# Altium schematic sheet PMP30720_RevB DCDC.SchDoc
size 431 x 279 mm; Date: Not shown in title block; ApprovedBy: Not shown in title block; CheckedBy: Not shown in title block; Author: Not shown in title block; CompanyName: Not shown in title block; Engineer: Not shown in title block; Organization: Not shown in title block; Address1: Not shown in title block; Address2: Not shown in title block; Address3: Not shown in title block; Address4: Not shown in title block; DocumentNumber: 1; Revision: Use project parameter SCH_Rev; SheetNumber: 1; SheetTotal: 1; PageSetup: Record=PageOptions¦CenterHorizontal=True¦CenterVertical=True¦PrintScale=1.00¦XCorrection=1.00¦YCorrection=1.00¦PrintKind=0¦BorderSize=5000000¦LeftOffset=0¦BottomOffset=0¦Orientation=2¦PaperLength=1000¦PaperWidth=1000¦Scale=100¦PaperSource=15¦PrintQuality=600¦MediaType=1¦DitherType=10¦PaperKind=Letter¦PrintScaleMode=1
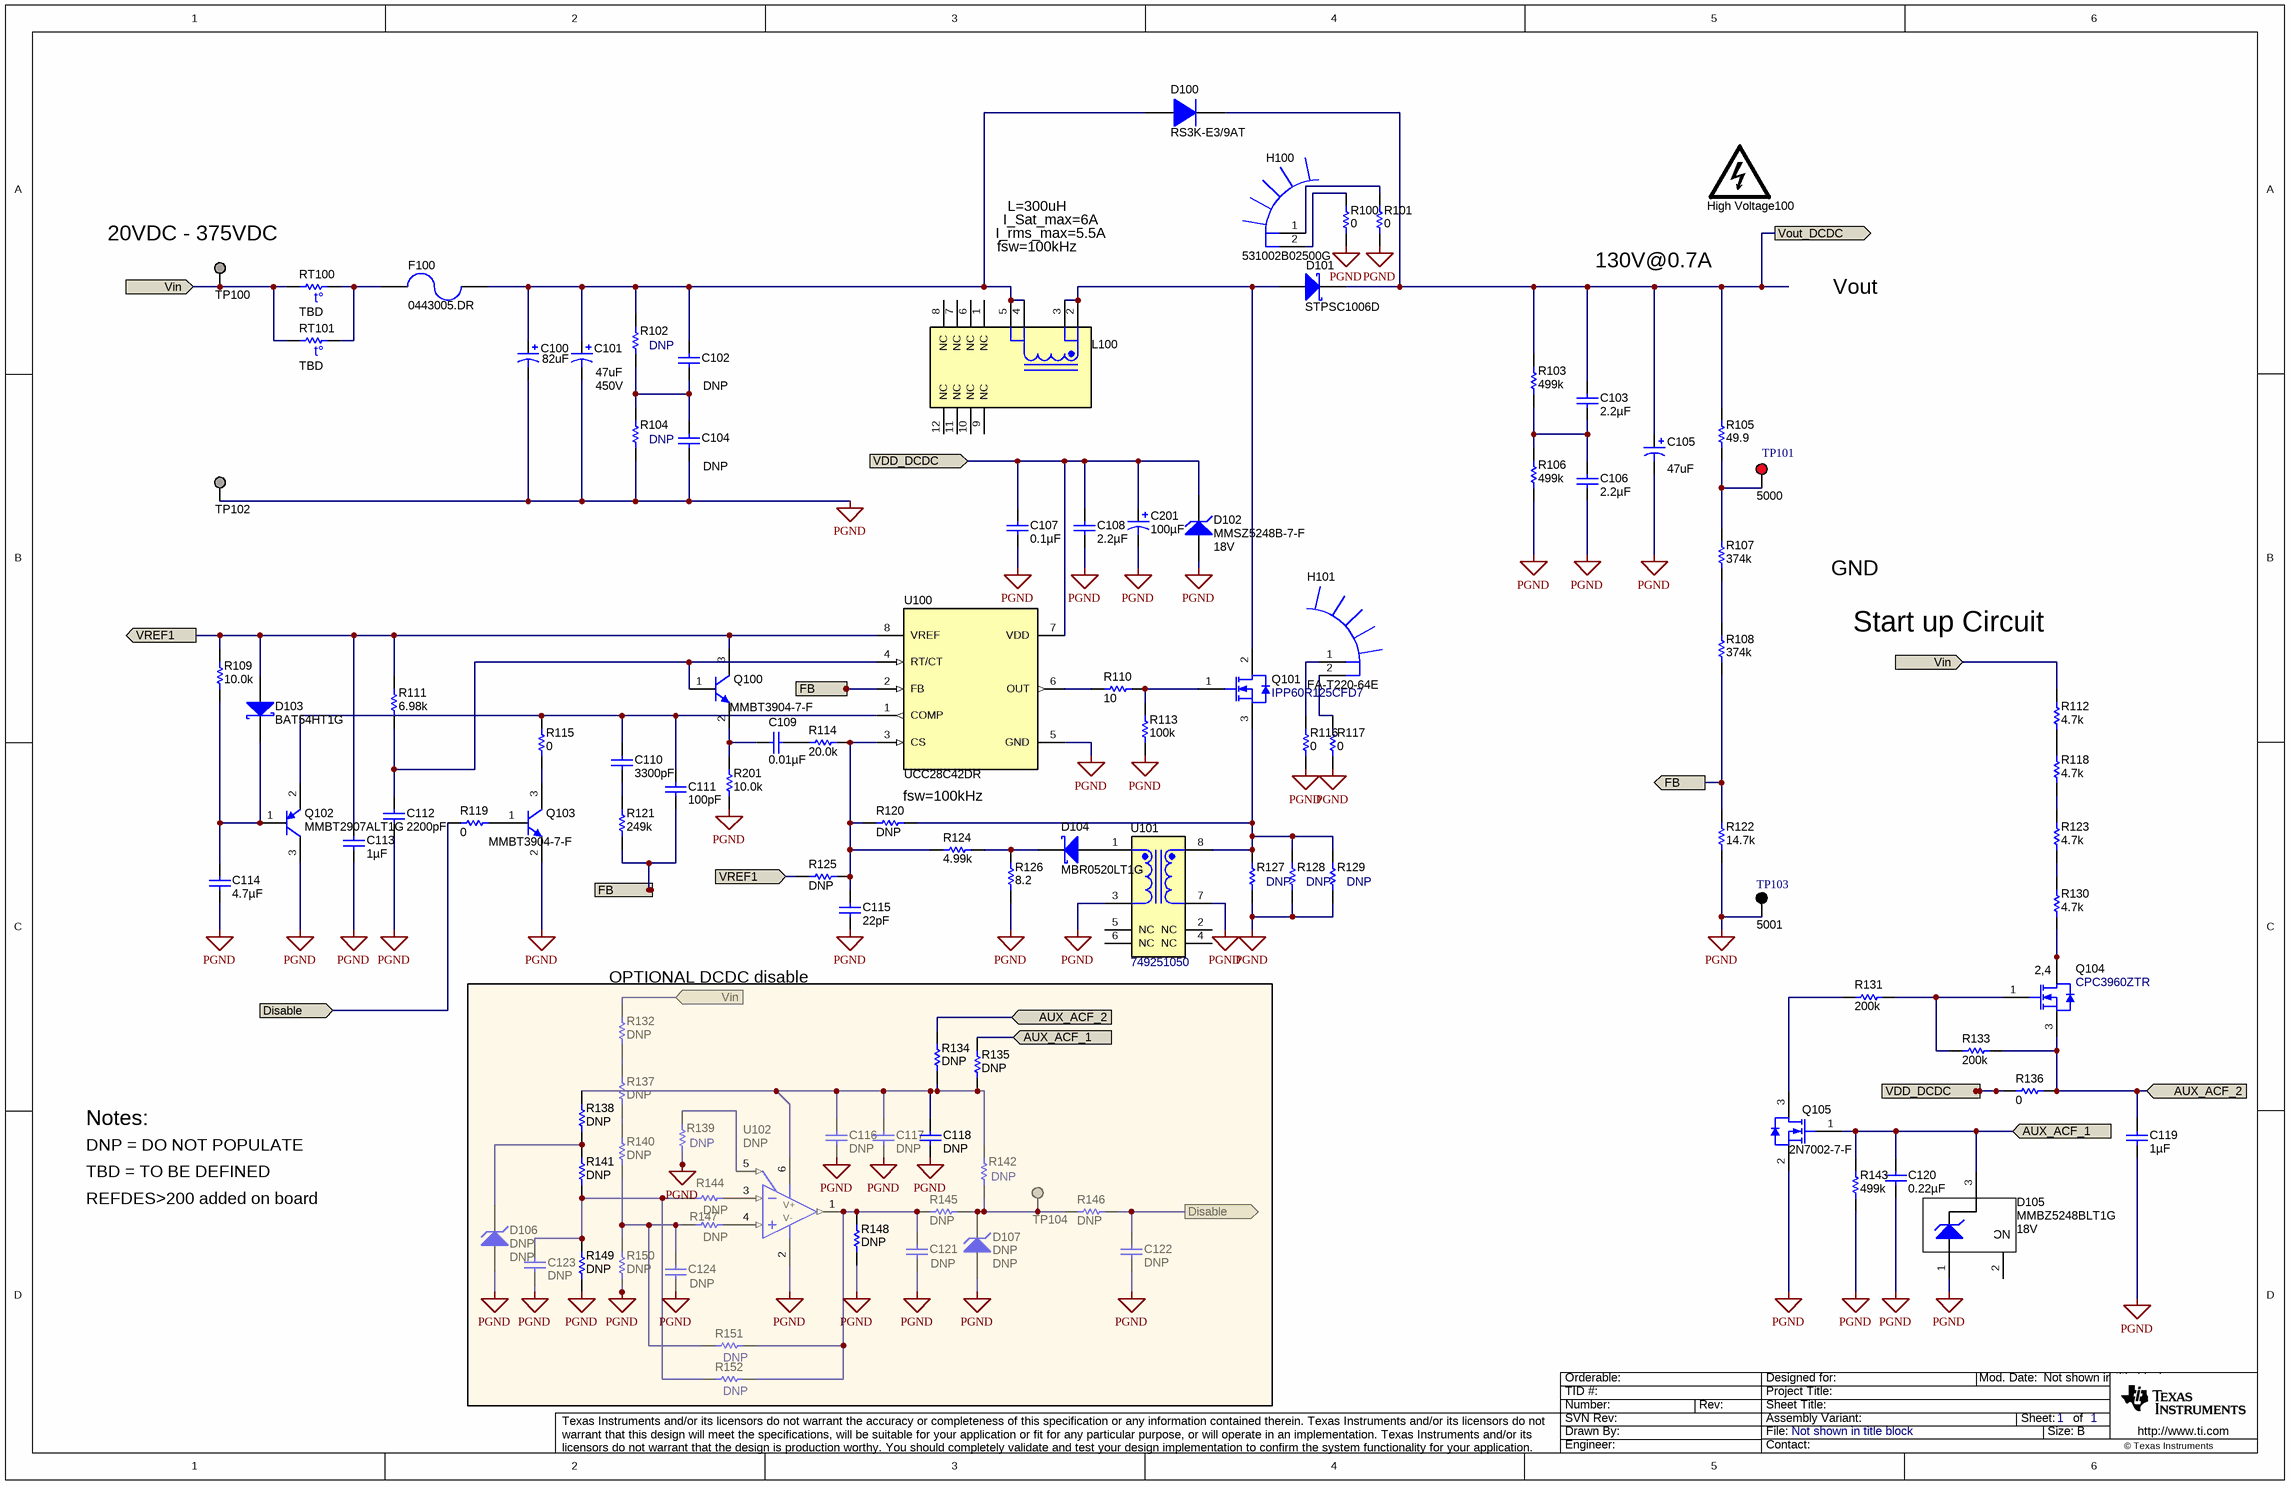
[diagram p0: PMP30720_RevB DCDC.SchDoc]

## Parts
C100  value 82uF  [CAPPR7.5-18x31.5]  (hidden comment: 450BXW82MEFR18X30)
C101  value 47uF  VDC_V: 450V  [CAPPR7.5-16x31.5]  (hidden comment: UVK2W470MHD)
C102  DNP  [2220]
C103  ValueDisplayed: 2.2µF  [CKG57N]  (hidden comment: CKG57NX7R2E225M500JH)
C104  DNP  [2220]
C105  ValueDisplayed: 47uF  [EE_1800x2000]  (hidden comment: EEU-EE2G470S)
C106  ValueDisplayed: 2.2µF  [CKG57N]  (hidden comment: CKG57NX7R2E225M500JH)
C107  ValueDisplayed: 0.1µF  [0603]  (hidden comment: GCM188R71H104KA57D)
C108  ValueDisplayed: 2.2µF  [1206]  (hidden comment: GRM31MR71E225KA93L)
C109  ValueDisplayed: 0.01µF  [0603]  (hidden comment: C0603C103J5RACTU)
C110  ValueDisplayed: 3300pF  [0603]  (hidden comment: GRM188R71H332KA01D)
C111  ValueDisplayed: 100pF  [0603]  (hidden comment: 06035A101FAT2A)
C112  ValueDisplayed: 2200pF  [0603]  (hidden comment: C0603C222K5RAC)
C113  ValueDisplayed: 1µF  [0805_HV]  (hidden comment: GRM21BR71C105KA01L)
C114  ValueDisplayed: 4.7µF  [1206_180]  (hidden comment: GRM31CR71E475KA88L)
C115  ValueDisplayed: 22pF  [0603]  (hidden comment: GRM1885C1H220JA01D)
C116  DNP  [0603]
C117  DNP  [1206]
C118  DNP  [1206]
C119  ValueDisplayed: 1µF  [1206]  (hidden comment: GRM31MR71H105KA88L)
C120  ValueDisplayed: 0.22µF  [0805_HV]  (hidden comment: GRM21BR71H224KA01L)
C121  value DNP  [0603]  (hidden comment: Used in BOM report)
C122  DNP  [0603]
C123  DNP  [1206]
C124  DNP  [0805]
C201  ValueDisplayed: 100µF  [CAPSMT_62_JA0]  (hidden comment: EMVH350ADA101MJA0G)
D100  RS3K-E3/9AT  [SMC]
D101  STPSC1006D  [TO-220-2]
D102  MMSZ5248B-7-F  value 18V  [SOD-123]
D103  BAT54HT1G  [SOD-323]
D104  MBR0520LT1G  [SOD-123]
D105  MMBZ5248BLT1G  value 18V  [SOT-23]
D106  DNP  [SOD-323]
D107  DNP  [SOD-123]
F100  0443005.DR  [FUSE_0443]
H100  531002B02500G  [HSINK_531002B02500G]
H101  FA-T220-64E  [HSINK_FA-T220-64E]
High_Voltage100  DANGER HIGH VOLTAGE  [IEC_HighVoltage_Medium]  (value not drawn)  (no BOM)
L100  750318149  [750318149]  (value not drawn)
Q100  MMBT3904-7-F  [SOT-23]
Q101  IPP60R125CFD7  [TO-220AB]
Q102  MMBT2907ALT1G  [SOT-23]
Q103  MMBT3904-7-F  [SOT-23]
Q104  CPC3960ZTR  [SOT-223]
Q105  2N7002-7-F  [SOT-23]
R100  ValueDisplayed: 0  [0805_HV]  (hidden comment: CRCW08050000Z0EA)
R101  ValueDisplayed: 0  [0805_HV]  (hidden comment: CRCW08050000Z0EA)
R102  DNP  [1206]
R103  ValueDisplayed: 499k  [1206]  (hidden comment: CRCW1206499KFKEA)
R104  DNP  [1206]
R105  ValueDisplayed: 49.9  [0805_HV]  (hidden comment: CRCW080549R9FKEA)
R106  ValueDisplayed: 499k  [1206]  (hidden comment: CRCW1206499KFKEA)
R107  ValueDisplayed: 374k  [0805_HV]  (hidden comment: CRCW0805374KFKEA)
R108  ValueDisplayed: 374k  [0805_HV]  (hidden comment: CRCW0805374KFKEA)
R109  ValueDisplayed: 10.0k  [0603]  (hidden comment: CRCW060310K0FKEA)
R110  ValueDisplayed: 10  [0805_HV]  (hidden comment: CRCW080510R0JNEA)
R111  ValueDisplayed: 6.98k  [0603]  (hidden comment: CRCW06036K98FKEA)
R112  ValueDisplayed: 4.7k  [2512]  (hidden comment: CRCW25124K70JNEG)
R113  ValueDisplayed: 100k  [0805_HV]  (hidden comment: CRCW0805100KFKEA)
R114  ValueDisplayed: 20.0k  [0603]  (hidden comment: CRCW060320K0FKEA)
R115  ValueDisplayed: 0  [0603]  (hidden comment: CRCW06030000Z0EA)
R116  ValueDisplayed: 0  [0805_HV]  (hidden comment: CRCW08050000Z0EA)
R117  ValueDisplayed: 0  [0805_HV]  (hidden comment: CRCW08050000Z0EA)
R118  ValueDisplayed: 4.7k  [2512]  (hidden comment: CRCW25124K70JNEG)
R119  ValueDisplayed: 0  [0603]  (hidden comment: CRCW06030000Z0EA)
R120  DNP  [0603]
R121  ValueDisplayed: 249k  [0603]  (hidden comment: CRCW0603249KFKEA)
R122  ValueDisplayed: 14.7k  [0603]  (hidden comment: CRCW060314K7FKEA)
R123  ValueDisplayed: 4.7k  [2512]  (hidden comment: CRCW25124K70JNEG)
R124  ValueDisplayed: 4.99k  [0603]  (hidden comment: CRCW06034K99FKEA)
R125  DNP  [0603]
R126  ValueDisplayed: 8.2  [1206]  (hidden comment: CRCW12068R20JNEA)
R127  DNP  [1210]
R128  DNP  [1210]
R129  DNP  [1210]
R130  ValueDisplayed: 4.7k  [2512]  (hidden comment: CRCW25124K70JNEG)
R131  ValueDisplayed: 200k  [0805_HV]  (hidden comment: CRCW0805200KJNEA)
R132  DNP  [1206]
R133  ValueDisplayed: 200k  [0805_HV]  (hidden comment: CRCW0805200KJNEA)
R134  DNP  [0805_HV]
R135  DNP  [0805_HV]
R136  ValueDisplayed: 0  [0805_HV]  (hidden comment: CRCW08050000Z0EAHP)
R137  DNP  [1206]
R138  DNP  [0603]
R139  value DNP  [0603]  (hidden comment: Used in BOM report)
R140  DNP  [1206]
R141  DNP  [0603]
R142  value DNP  [0805]  (hidden comment: Used in BOM report)
R143  ValueDisplayed: 499k  [0805_HV]  (hidden comment: CRCW0805499KFKEA)
R144  DNP  [0603]
R145  DNP  [0805_HV]
R146  DNP  [0805_HV]
R147  DNP  [0603]
R148  DNP  [0603]
R149  DNP  [0603]
R150  DNP  [0805_HV]
R151  DNP  [0805]
R152  DNP  [0805]
R201  ValueDisplayed: 10.0k  [0603]  (hidden comment: CRCW060310K0FKEA)
RT100  TBD  [S237]
RT101  TBD  [S237]
TP100  Suggest using a net name here  [Keystone1503-2]  (value not drawn)
TP101  5000  [Keystone5000]
TP102  Suggest using a net name here  [Keystone1503-2]  (value not drawn)
TP103  5001  [Keystone5001]
TP104  1508-0-57-15-00-00-03-0  [Mill-Max_1508]  (value not drawn)
U100  UCC28C42DR  [D0008A_N]
U101  749251050  [Wurth_WE-CST_EF5]
U102  PartNumber: DNP  [DBV0006A_N]  (hidden comment: TLV1805DBVR)

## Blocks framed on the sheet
OPTIONAL DCDC disable: C116-C118 C121-C124 D106 D107 R132 R134 R135 R137-R142 R144-R152 TP104 U102

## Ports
AUX_ACF_1 (in), AUX_ACF_2 (in), Disable (in), Disable (out), FB (in), FB (out), VDD_DCDC (in), VDD_DCDC (out), Vin (in), Vout_DCDC (out), VREF1 (in), VREF1 (out)

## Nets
PGND: C100.2(-) C101.2(-) C104.2 C105.2(-) C106.2 C107.2 C108.2 C112.2 C113.2 C114.2 C115.2 C116.2 C117.2 C118.2 C119.2 C120.2 C121.2 C122.2 C123.2 C124.2 C201.2(-) D102.2(A) D105.1(A) D106.2(A) D107.2(A) Q102.3(C) Q103.2(E) Q105.2(S) R100.1 R101.1 R104.1 R106.1 R113.1 R116.1 R117.1 R122.1 R126.1 R127.1 R128.1 R129.1 R139.1 R143.1 R148.1 R149.1 R150.1 R201.1 TP102.1 TP103.1 U100.5(GND) U101.3 U101.7 U102.2(V-)
AUX_ACF_1: C120.1 D105.3(K) Q105.1(G) R135.2 R143.2 ; port AUX_ACF_1
AUX_ACF_2: C119.1 Q104.3(S) R133.1 R134.2 R136.2 ; port AUX_ACF_2
Disable: C122.1 R119.2 R146.2 ; port Disable
FB: R108.1 R122.2 U100.2(FB) ; port FB
VDD_DCDC: C107.1 C108.1 C201.1(+) D102.1(K) R136.1 U100.7(VDD) ; port VDD_DCDC
Vin: R112.2 R132.2 RT100.1 RT101.1 TP100.1 ; port Vin
Vout_DCDC: C103.1 C105.1(+) D100.1(K) D101.1(K) R103.2 R105.2 ; port Vout_DCDC
VREF1: C113.1 D103.2(A) Q100.3(C) R109.2 R111.2 R125.1 U100.8(VREF) ; port VREF1
NetC100_1: C100.1(+) C101.1(+) C102.1 D100.2(A) F100.1 L100.4 L100.5 R102.2
NetC102_2: C102.2 C104.1 R102.1 R104.2
NetC103_2: C103.2 C106.1 R103.1 R106.2
NetC109_1: C109.1 R114.1
NetC109_2: C109.2 Q100.2(E) R201.2
NetC110_1: C110.1 C111.1 Q102.2(E) R115.2 U100.1(COMP)
NetC110_2: C110.2 R121.2
NetC111_2: C111.2 R121.1
NetC112_1: C112.1 Q100.1(B) R111.1 U100.4(RT/CT)
NetC114_1: C114.1 D103.1(K) Q102.1(B) R109.1
NetC115_1: C115.1 R114.2 R120.1 R124.1 R125.2 U100.3(CS)
NetC116_1: C116.1 C117.1 C118.1 R134.1 R135.1 R138.2 R142.2 U102.6(V+)
NetC121_1: C121.1 R145.1 R148.2 R151.2 R152.2 U102.1(OUT)
NetC123_1: C123.1 R141.1 R144.1 R149.2 R152.1
NetC124_1: C124.1 R140.1 R147.1 R150.2 R151.1
NetD101_2: D101.2(A) L100.2 L100.3 Q101.2(D)
NetD104_1: D104.1(K) R124.2 R126.2
NetD104_2: D104.2(A) U101.1
NetD106_1: D106.1(K) R138.1 R141.2
NetD107_1: D107.1(K) R142.1 R145.2 R146.1 TP104.1
NetF100_2: F100.2 RT100.2 RT101.2
NetH100_1: H100.1 R101.2
NetH100_2: H100.2 R100.2
NetH101_1: H101.1 R116.2
NetH101_2: H101.2 R117.2
NetQ101_1: Q101.1(G) R110.2 R113.2
NetQ101_3: Q101.3(S) R120.2 R127.2 R128.2 R129.2 U101.8
NetQ103_1: Q103.1(B) R119.1
NetQ103_3: Q103.3(C) R115.1
NetQ104_1: Q104.1(G) R131.1 R133.2
NetQ104_2: Q104.2(D) Q104.4(D) R130.1
NetQ105_3: Q105.3(D) R131.2
NetR105_1: R105.1 R107.2 TP101.1
NetR107_1: R107.1 R108.2
NetR110_1: R110.1 U100.6(OUT)
NetR112_1: R112.1 R118.2
NetR118_1: R118.1 R123.2
NetR123_1: R123.1 R130.2
NetR132_1: R132.1 R137.2
NetR137_1: R137.1 R140.2
NetR139_2: R139.2 U102.5(SD)
NetR144_2: R144.2 U102.3(IN-)
NetR147_2: R147.2 U102.4(IN+)

Not connected (* = marked no-connect by the designer): D105 2(NC); L100 1(NC) 6(NC) 7(NC) 8(NC) 9(NC) 10(NC) 11(NC) 12(NC); U101 2(NC) 4(NC) 5(NC) 6(NC)

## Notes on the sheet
- (near TP100) 20VDC - 375VDC
- L=300uH
- I_Sat_max=6A
- I_rms_max=5.5A
- fsw=100kHz
- 130V@0.7A
- Vout
- GND
- Start up Circuit
- (near R120) fsw=100kHz
- Notes:
- DNP = DO NOT POPULATE
- TBD = TO BE DEFINED
- REFDES>200 added on board

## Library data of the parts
C100 = Capacitor_Polarized: CAP, [Technology], 82uF, 450V, +/-xx%, xxOhm ESR, [MountType]; Manufacturer: Used in BOM report; Polarized: Y; U/M: EA
C101 = Capacitor_Polarized: CAP, [Technology], 47uF, 450V, +/-xx%, xxOhm ESR, [MountType]; Manufacturer: Nichicon; Polarized: Y; U/M: EA
C102 C104 C124 = Capacitor: CAP, CERM, xxxF, xxV, [TempCo], xx%, [PackageReference]; Manufacturer: Used in BOM report; Polarized: N; U/M: EA
C103 C106 = CKG57NX7R2E225M500JH: CAP, CERM, 2.2 µF, 250 V,+/- 20%, X7R, AEC-Q200 Grade 1, 6x5x5mm; Manufacturer: TDK; Polarized: N; CompType: Capacitor; Value: 2.2uF; U/M: EA; Cap_F: 0.0000022; Tolerance_%: 20; VDC_V: 250; Value2: 250V; TaMin_C: -55; TaMax_C: 125; Cap_Case: 2220; SizeArea_mm2: 30; SizeAreaWB_mm2: 56; SizeX_mm: 6; SizeY_mm: 5; SizeZ_mm: 5.5; AEC Category: Q200; AEC Qualified: Y; AEC Grade: 1
C105 = CMP-0010026-1: CAP, AL, 47 uF, 400 V, +/- 20%, TH; Manufacturer: Panasonic; TaMin_C: -25°C; Polarized: Y; SizeAreaWB_mm2: 400; Value1: Unknown; U/M: EA; Value: 47uF; TaMax_C: 105°C; SizeZ_mm: 22; SizeX_mm: 18; Cap_Case: 18x20; Value2: 400V; SizeArea_mm2: 324; CompType: Capacitor; AEC Qualified: N; Cap_F: 47µF; IRMS_A: 1.18A; AEC Category: Q200
C107 = GCM188R71H104KA57D: CAP, CERM, 0.1 µF, 50 V,+/- 10%, X7R, 0603; Manufacturer: MuRata; Polarized: N; CompType: Capacitor; Value: 0.1uF; U/M: EA; Cap_F: 0.0000001; Tolerance_%: 10; ESR_ohm: 0.02; Value1: 0.02 ohm; VDC_V: 50; Value2: 50V; IRMS_A: 1.84; TaMin_C: -55; TaMax_C: 125; SizeArea_mm2: 1.28; SizeAreaWB_mm2: 4.68; SizeX_mm: 1.6; SizeY_mm: 0.8; SizeZ_mm: 1; AEC Category: Q200; Green_Lifecycle: Active; Green_REACh: Passed
C108 = GRM31MR71E225KA93L: CAP, CERM, 2.2 µF, 25 V,+/- 10%, X7R, 1206; Manufacturer: MuRata; Polarized: N; CompType: Capacitor; Value: 2.2uF; U/M: EA; Cap_F: 0.0000022; Tolerance_%: 10; VDC_V: 25; Value2: 25V; TaMin_C: -55; TaMax_C: 125; SizeArea_mm2: 5.12; SizeAreaWB_mm2: 10.92; SizeX_mm: 3.2; SizeY_mm: 1.6; SizeZ_mm: 1.35; AEC Category: Q200; Green_Lifecycle: Active; Green_REACh: Passed
C109 = C0603C103J5RACTU: CAP, CERM, 0.01 µF, 50 V,+/- 5%, X7R, 0603; Manufacturer: Kemet; Polarized: N; CompType: Capacitor; Value: 0.01uF; U/M: EA; Cap_F: 0.00000001; Tolerance_%: 5; VDC_V: 50; Value2: 50V; TaMin_C: -55; TaMax_C: 125; SizeArea_mm2: 1.28; SizeAreaWB_mm2: 4.68; SizeX_mm: 1.6; SizeY_mm: 0.8; SizeZ_mm: 1; AEC Category: Q200; Green_Lifecycle: Active; Green_REACh: Passed
C110 = GRM188R71H332KA01D: CAP, CERM, 3300 pF, 50 V,+/- 10%, X7R, 0603; Manufacturer: MuRata; Polarized: N; CompType: Capacitor; Value: 3300pF; U/M: EA; Cap_F: 0.0000000033; Tolerance_%: 10; VDC_V: 50; Value2: 50V; TaMin_C: -55; TaMax_C: 125; SizeArea_mm2: 1.28; SizeAreaWB_mm2: 4.68; SizeX_mm: 1.6; SizeY_mm: 0.8; SizeZ_mm: 1; AEC Category: Q200; Green_Lifecycle: Active; Green_REACh: Passed
C111 = 06035A101FAT2A: CAP, CERM, 100 pF, 50 V,+/- 1%, C0G/NP0, 0603; Manufacturer: AVX; Polarized: N; CompType: Capacitor; Value: 100pF; U/M: EA; Cap_F: 0.0000000001; Tolerance_%: 1; VDC_V: 50; Value2: 50V; TaMin_C: -55; TaMax_C: 125; SizeArea_mm2: 1.28; SizeAreaWB_mm2: 4.68; SizeX_mm: 1.6; SizeY_mm: 0.8; AEC Category: Q200; Green_Lifecycle: Active; Green_REACh: Passed
C112 = C0603C222K5RAC: CAP, CERM, 2200 pF, 50 V,+/- 10%, X7R, 0603; Manufacturer: Kemet; Polarized: N; CompType: Capacitor; Value: 2200pF; U/M: EA; Cap_F: 0.0000000022; Tolerance_%: 10; VDC_V: 50; Value2: 50V; TaMin_C: -55; TaMax_C: 125; SizeArea_mm2: 1.28; SizeAreaWB_mm2: 4.68; SizeX_mm: 1.6; SizeY_mm: 0.8; SizeZ_mm: 1; AEC Category: Q200; Green_Lifecycle: Active; Green_REACh: Passed
C113 = GRM21BR71C105KA01L: CAP, CERM, 1 µF, 16 V,+/- 10%, X7R, 0805; Manufacturer: MuRata; Polarized: N; CompType: Capacitor; Value: 1uF; U/M: EA; Cap_F: 0.000001; Tolerance_%: 10; ESR_ohm: 0.003; Value1: 0.003 ohm; VDC_V: 16; Value2: 16V; TaMin_C: -55; TaMax_C: 125; Cap_Case: 0805; SizeArea_mm2: 2.5; SizeAreaWB_mm2: 6.75; SizeX_mm: 2; SizeY_mm: 1.25; SizeZ_mm: 1.45; AEC Category: Q200; Green_Lifecycle: Active; Green_REACh: Passed
C114 = GRM31CR71E475KA88L: CAP, CERM, 4.7 µF, 25 V,+/- 10%, X7R, 1206; Manufacturer: MuRata; Polarized: N; CompType: Capacitor; Value: 4.7uF; U/M: EA; Cap_F: 0.0000047; Tolerance_%: 10; VDC_V: 25; Value2: 25V; TaMin_C: -55; TaMax_C: 125; Cap_Case: 1206; SizeArea_mm2: 5.12; SizeAreaWB_mm2: 10.92; SizeX_mm: 3.2; SizeY_mm: 1.6; SizeZ_mm: 1.8; AEC Category: Q200; Green_Lifecycle: Active; Green_REACh: Passed
C115 = GRM1885C1H220JA01D: CAP, CERM, 22 pF, 50 V,+/- 5%, C0G/NP0, 0603; Manufacturer: MuRata; Polarized: N; CompType: Capacitor; Value: 22pF; U/M: EA; Cap_F: 0.000000000022; Tolerance_%: 5; VDC_V: 50; Value2: 50V; TaMin_C: -55; TaMax_C: 125; SizeArea_mm2: 1.28; SizeAreaWB_mm2: 4.68; SizeX_mm: 1.6; SizeY_mm: 0.8; SizeZ_mm: 1; AEC Category: Q200; Green_Lifecycle: Active; Green_REACh: Passed
C116 = GRM188R71H104KA93D: CAP, CERM, 0.1 µF, 50 V,+/- 10%, X7R, 0603; Manufacturer: MuRata; Polarized: N; CompType: Capacitor; U/M: EA; Cap_F: 0.0000001; Tolerance_%: 10; VDC_V: 50; Value2: 50V; TaMin_C: -55; TaMax_C: 125; SizeArea_mm2: 1.28; SizeAreaWB_mm2: 4.68; SizeX_mm: 1.6; SizeY_mm: 0.8; SizeZ_mm: 1; AEC Category: Q200; Green_Lifecycle: Active; Green_REACh: Passed
C117 C118 C123 = GRM31MR71H105KA88L: CAP, CERM, 1 µF, 50 V,+/- 10%, X7R, 1206; Manufacturer: MuRata; Polarized: N; CompType: Capacitor; U/M: EA; Cap_F: 0.000001; Tolerance_%: 10; VDC_V: 50; Value2: 50V; TaMin_C: -55; TaMax_C: 125; SizeArea_mm2: 5.12; SizeAreaWB_mm2: 10.92; SizeX_mm: 3.2; SizeY_mm: 1.6; SizeZ_mm: 1.35; AEC Category: Q200; Green_Lifecycle: Active; Green_REACh: Passed
C119 = GRM31MR71H105KA88L: CAP, CERM, 1 µF, 50 V,+/- 10%, X7R, 1206; Manufacturer: MuRata; Polarized: N; CompType: Capacitor; Value: 1uF; U/M: EA; Cap_F: 0.000001; Tolerance_%: 10; VDC_V: 50; Value2: 50V; TaMin_C: -55; TaMax_C: 125; SizeArea_mm2: 5.12; SizeAreaWB_mm2: 10.92; SizeX_mm: 3.2; SizeY_mm: 1.6; SizeZ_mm: 1.35; AEC Category: Q200; Green_Lifecycle: Active; Green_REACh: Passed
C120 = GRM21BR71H224KA01L: CAP, CERM, 0.22 µF, 50 V,+/- 10%, X7R, 0805; Manufacturer: MuRata; Polarized: N; CompType: Capacitor; Value: 0.22uF; U/M: EA; Cap_F: 0.00000022; Tolerance_%: 10; VDC_V: 50; Value2: 50V; TaMin_C: -55; TaMax_C: 125; Cap_Case: 0805; SizeArea_mm2: 2.5; SizeAreaWB_mm2: 6.75; SizeX_mm: 2; SizeY_mm: 1.25; SizeZ_mm: 1.45; AEC Category: Q200; Green_Lifecycle: Active; Green_REACh: Passed
C121 = Capacitor: CAP, CERM, xxxF, xxV, [TempCo], xx%, [PackageReference]; Polarized: N; U/M: EA
C122 = GRM1885C1H101JA01D: CAP, CERM, 100 pF, 50 V,+/- 5%, C0G/NP0, 0603; Manufacturer: MuRata; Polarized: N; CompType: Capacitor; U/M: EA; Cap_F: 0.0000000001; Tolerance_%: 5; VDC_V: 50; Value2: 50V; TaMin_C: -55; TaMax_C: 125; SizeArea_mm2: 1.28; SizeAreaWB_mm2: 4.68; SizeX_mm: 1.6; SizeY_mm: 0.8; SizeZ_mm: 1; AEC Category: Q200; Green_Lifecycle: Active; Green_REACh: Passed
C201 = EMVH350ADA101MJA0G: CAP, AL, 100 µF, 35 V, +/- 20%, 0.3 ohm, SMD; Manufacturer: Chemi-Con; Polarized: Y; CompType: Capacitor; Value: 100uF; U/M: EA; Cap_F: 0.0001; Tolerance_%: 20; Value1: 0.3 ohm; VDC_V: 35; Value2: 35V; ESR_ohm: 0.3; IRMS_A: 0.296; TaMin_C: -40; TaMax_C: 125; Cap_Case: JA0; SizeAreaWB_mm2: 151.29; SizeArea_mm2: 106.09; SizeX_mm: 10.3; SizeZ_mm: 10; AEC Category: Q200
D100 = RS3K-E3/9AT: Diode, Switching, 800 V, 3 A, SMC; Manufacturer: Vishay-Semiconductor; U/M: EA; Vf_V: 1.3; Value: 800V; Value1: 3A; Value2: 1.3V; Io_A: 3; Vr_V: 800; TJmax_C: 150; RJC_CperW: 50; SizeAreaWB_mm2: 83.2686; SizeArea_mm2: 50.5686; SizeX_mm: 8.13; SizeY_mm: 6.22; SizeZ_mm: 2.6; AEC Category: Q101
D101 = APT20SCD65K: Diode, Schottky, 600 V,; Manufacturer: Microsemi; U/M: EA; Value: 600V; Io_A: 32; Vr_V: 600; TJmax_C: 150; RJC_CperW: 1.1; SizeAreaWB_mm2: 77.630025; SizeArea_mm2: 44.650025; SizeX_mm: 10.045; SizeY_mm: 4.445; SizeZ_mm: 20; AEC Category: Q101; AEC Qualified: N
D102 = MMSZ5248B-7-F: Diode, Zener, 18 V, 500 mW, SOD-123; Manufacturer: Diodes Inc.; SymbolCreator: a0412235; U/M: EA; Power_W: 0.5; Vz_V: 18; Value1: 0.5W; RJA_CperW: 350; SizeAreaWB_mm2: 13.095; SizeArea_mm2: 6.545; SizeX_mm: 3.85; SizeY_mm: 1.7; SizeZ_mm: 1.35; AEC Category: Q101; Green_Lifecycle: Active; Green_REACh: Passed
D103 = BAT54HT1G: Diode, Schottky, 30 V, 0.2 A, SOD-323; Manufacturer: ON Semiconductor; U/M: EA; Vf_V: 0.35; Value: 30V; Value1: 0.2A; Value2: 0.35V; Io_A: 0.2; Vr_V: 30; SizeAreaWB_mm2: 8.695; SizeArea_mm2: 3.645; SizeX_mm: 2.7; SizeY_mm: 1.35; SizeZ_mm: 1; AEC Category: Q101; Green_Lifecycle: Active; Green_REACh: Passed
D104 = MBR0520LT1G: Diode, Schottky, 20 V, 0.5 A, SOD-123; Manufacturer: ON Semiconductor; U/M: EA; Vf_V: 0.385; Value: 20V; Value1: 0.5A; Value2: 0.385V; Io_A: 0.5; Vr_V: 20; TJmax_C: 125; RJC_CperW: 150; SizeAreaWB_mm2: 13.095; SizeArea_mm2: 6.545; SizeX_mm: 3.85; SizeY_mm: 1.7; SizeZ_mm: 1.35; AEC Category: Q101; Green_Lifecycle: Active; Green_REACh: Passed
D105 = MMBZ5248BLT1G: Diode, Zener, 18 V, 225 mW, SOT-23; Manufacturer: ON Semiconductor; U/M: EA; Power_W: 0.225; Vz_V: 18; Value1: 0.225W; RJA_CperW: 556; SizeAreaWB_mm2: 14; SizeArea_mm2: 7.5; SizeX_mm: 2.5; SizeY_mm: 3; SizeZ_mm: 1.1; AEC Category: Q101
D106 = MMSZ5240BS-7-F: Diode, Zener, 10 V, 200 mW, SOD-323; Manufacturer: Diodes Inc.; SymbolCreator: a0412235; U/M: EA; Power_W: 0.2; Vz_V: 10; Value1: 0.2W; RJA_CperW: 350; SizeAreaWB_mm2: 8.695; SizeArea_mm2: 3.645; SizeX_mm: 2.7; SizeY_mm: 1.35; SizeZ_mm: 1; AEC Category: Q101
D107 = MMSZ4688T1G: Diode, Zener, 4.7 V, 500 mW, SOD-123; Manufacturer: ON Semiconductor; SymbolCreator: a0412235; U/M: EA; Power_W: 0.5; Vz_V: 4.7; Value1: 0.5W; RJA_CperW: 340; SizeAreaWB_mm2: 13.095; SizeArea_mm2: 6.545; SizeX_mm: 3.85; SizeY_mm: 1.7; SizeZ_mm: 1.35; AEC Category: Q101
F100 = 0443003.DR: Fuse, 5 A, 250VAC/VDC, SMD; Manufacturer: Littelfuse; VDC_V: 250; Interrupt_AC: 50; Irating_A: 5; Rtyp_Ohm: 0.028; MeltingTyp: 51.44
H100 = 531002B02500G: HEATSINK TO-220 W/PINS 1" TALL; Manufacturer: Aavid; SymbolCreator: a0799628; Green_Lifecycle: Not Set; Green_REACh: Incomplete
H101 = FA-T220-64E: Heatsink, TO-220, TO-218, TO-247; Manufacturer: Ohmite; SymbolCreator: a0799628
High_Voltage100 = IEC_HighVoltage: IEC 61010-1 High Voltage Warning; SymbolCreator: a0412235
L100 = CMP-0086236-1: Inductor, 300 µH, 0.065 ohm, TH; Manufacturer: Wurth Elektronik; DCR_ohm: 0.065; SizeZ_mm: 38.1; SizeX_mm: 40.64; SizeAreaWB_mm2: 1628.848; Ind_H: 300µH; AEC Qualified: N; Value2: A; Value: 300uH; SizeArea_mm2: 1471.168; AEC Category: Q200; SizeY_mm: 36.2
Q100 Q103 = MMBT3904-7-F, Diodes Inc.: Transistor, NPN, 40 V, 0.2 A, SOT-23; CompType: BJT; PNP: 0; NPN: 1; Vceo_V: 40; Vcesat1_V: 0.2; Value: 40 V; Value1: 0.2 A; HfeMax: 400; TaMin_C: -55; TaMax_C: 150; SizeAreaWB_mm2: 14; SizeArea_mm2: 7.5; SizeX_mm: 2.5; SizeY_mm: 3; SizeZ_mm: 1.1; U/M: EA; AEC Category: Q101; Green_Lifecycle: Active; Green_REACh: Passed
Q101 = CMP-0001173-3: MOSFET, N-CH, 600 V, 25 A, TO-220AB; Alternate Manufacturer: None; Manufacturer: Infineon Technologies; SizeZ_mm: 19.4; ChType: N; Value2: 53 nC; VdsMax_V: 600V; SizeX_mm: 10.2; SizeY_mm: 4.5; Vgs_V: 20V; Value: 600V; SizeArea_mm2: 45.9; AEC Category: Q101; IdsMax_A: 25A; SizeAreaWB_mm2: 79.3; U/M: EA; QgTyp_nC: 53
Q102 = MMBT2907ALT1G, ON Semiconductor: Transistor, PNP, 60 V, 0.6 A, SOT-23; CompType: BJT; PNP: 1; NPN: 0; Vceo_V: 60; Vcesat1_V: 1.6; Value: 60 V; IcRated_A: 0.6; Value1: 0.6 A; TaMin_C: -55; TaMax_C: 150; SizeAreaWB_mm2: 14; SizeArea_mm2: 7.5; SizeX_mm: 2.5; SizeY_mm: 3; SizeZ_mm: 1.1; U/M: EA; AEC Category: Q101; Green_Lifecycle: Active; Green_REACh: Passed
Q104 = CMP-0086195-1: MOSFET, N-CH, Depletion Mode, 600 V, 0.1 A, SOT-223; Alternate Manufacturer: None; Manufacturer: IXYS; AEC Qualified: N; SizeArea_mm2: 45.5; SizeZ_mm: 1.6; VdsMax_V: 600V; Value: 600V; Value2: ? nC; SizeX_mm: 6.5; Value1: ? ohm; SizeY_mm: 7; SizeAreaWB_mm2: 76.5; AEC Category: Q101; IdsMax_A: 100mA; Vgs_V: 15V
Q105 = 2N7002-7-F: MOSFET, N-CH, 60 V, 0.17 A, SOT-23; Manufacturer: Diodes Inc.; Alternate Manufacturer: None; U/M: EA; ChType: N; Value: 60V; VdsMax_V: 60; Value1: 7.5 ohm; Rdson45_ohm: 7.5; Value2: 223 nC; QgTyp_nC: 223; Vgs_V: 20; IdsMax_A: 0.17; SizeAreaWB_mm2: 14; SizeX_mm: 2.5; SizeY_mm: 3; SizeZ_mm: 1.1; AEC Category: Q101; Green_Lifecycle: Active; Green_REACh: Passed
R100 R101 R116 R117 = CRCW08050000Z0EA: RES, 0, 5%, 0.125 W, 0805; Manufacturer: Vishay-Dale; CompType: Resistor; Value: 0; Value_Code: 0000; Tolerance_%: 5; Power_W: 0.125; Value2: 0.125W; VDC_V: 150; TempCo: 200 ppm/C; SizeArea_mm2: 2.5; SizeX_mm: 2; SizeY_mm: 1.25; SizeZ_mm: 1.45; EIA_Code: E24; U/M: EA; AEC Category: Q200; Green_Lifecycle: Active; Green_REACh: Passed
R102 R104 R151 R152 = Resistor: RES, xxx ohm, x%, xW, [PackageReference]; Manufacturer: Used in BOM report; U/M: EA
R103 R106 = CRCW1206499KFKEA: RES, 499 k, 1%, 0.25 W, 1206; Manufacturer: Vishay-Dale; CompType: Resistor; Value: 499k; Res_ohm: 499000; Tolerance_%: 1; Power_W: 0.25; Value2: 0.25W; VDC_V: 200; TempCo: 100 ppm/C; SizeArea_mm2: 5.12; SizeX_mm: 3.2; SizeY_mm: 1.6; SizeZ_mm: 1.35; EIA_Code: E96; U/M: EA; AEC Category: Q200; Green_Lifecycle: Active; Green_REACh: Passed
R105 = CRCW080549R9FKEA: RES, 49.9, 1%, 0.125 W, 0805; Manufacturer: Vishay-Dale; CompType: Resistor; Value: 49.9; Value_Code: 49R9; Tolerance_%: 1; Power_W: 0.125; Value2: 0.125W; VDC_V: 150; TempCo: 100 ppm/C; SizeArea_mm2: 2.5; SizeX_mm: 2; SizeY_mm: 1.25; SizeZ_mm: 1.45; EIA_Code: E96; U/M: EA; AEC Category: Q200; Green_Lifecycle: Active; Green_REACh: Passed
R107 R108 = CRCW0805374KFKEA: RES, 374 k, 1%, 0.125 W, 0805; Manufacturer: Vishay-Dale; CompType: Resistor; Value: 374k; Res_ohm: 374000; Tolerance_%: 1; Power_W: 0.125; Value2: 0.125W; VDC_V: 150; TempCo: 100 ppm/C; SizeArea_mm2: 2.5; SizeX_mm: 2; SizeY_mm: 1.25; SizeZ_mm: 1.45; EIA_Code: E96; U/M: EA; AEC Category: Q200
R109 R201 = CRCW060310K0FKEA: RES, 10.0 k, 1%, 0.1 W, 0603; Manufacturer: Vishay-Dale; CompType: Resistor; Value: 10.0k; Res_ohm: 10000; Value_Code: 10k0; Tolerance_%: 1; Power_W: 0.1; Value2: 0.1W; VDC_V: 75; TempCo: 100 ppm/C; SizeArea_mm2: 1.28; SizeX_mm: 1.6; SizeY_mm: 0.8; EIA_Code: E96; U/M: EA; AEC Category: Q200; Green_Lifecycle: Active; Green_REACh: Passed
R110 = CRCW080510R0JNEA: RES, 10, 5%, 0.125 W, 0805; Manufacturer: Vishay-Dale; CompType: Resistor; Value: 10; Value_Code: 10R0; Tolerance_%: 5; Power_W: 0.125; Value2: 0.125W; VDC_V: 150; TempCo: 200 ppm/C; SizeArea_mm2: 2.5; SizeX_mm: 2; SizeY_mm: 1.25; SizeZ_mm: 1.45; EIA_Code: E24; U/M: EA; AEC Category: Q200; Green_Lifecycle: Active; Green_REACh: Passed
R111 = CRCW06036K98FKEA: RES, 6.98 k, 1%, 0.1 W, 0603; Manufacturer: Vishay-Dale; CompType: Resistor; Value: 6.98k; Res_ohm: 6980; Value_Code: 6k98; Tolerance_%: 1; Power_W: 0.1; Value2: 0.1W; VDC_V: 75; TempCo: 100 ppm/C; SizeArea_mm2: 1.28; SizeX_mm: 1.6; SizeY_mm: 0.8; EIA_Code: E96; U/M: EA; AEC Category: Q200; Green_Lifecycle: Active; Green_REACh: Passed
R112 R118 R123 R130 = CRCW25124K70JNEG: RES, 4.7 k, 5%, 1 W, AEC-Q200 Grade 0, 2512; Manufacturer: Vishay-Dale; CompType: Resistor; Value: 4.7k; Res_ohm: 4700; Value_Code: 4k70; Tolerance_%: 5; Power_W: 1; Value2: 1W; VDC_V: 500; TempCo: 200 ppm/C; SizeArea_mm2: 20.16; SizeX_mm: 6.3; SizeY_mm: 3.2; SizeZ_mm: 0.71; EIA_Code: E24; U/M: EA; AEC Category: Q200; AEC Qualified: Y; AEC Grade: 0
R113 = CRCW0805100KFKEA: RES, 100 k, 1%, 0.125 W, 0805; Manufacturer: Vishay-Dale; CompType: Resistor; Value: 100k; Res_ohm: 100000; Tolerance_%: 1; Power_W: 0.125; Value2: 0.125W; VDC_V: 150; TempCo: 100 ppm/C; SizeArea_mm2: 2.5; SizeX_mm: 2; SizeY_mm: 1.25; SizeZ_mm: 1.45; EIA_Code: E96; U/M: EA; AEC Category: Q200; Green_Lifecycle: Active; Green_REACh: Passed
R114 = CRCW060320K0FKEA: RES, 20.0 k, 1%, 0.1 W, 0603; Manufacturer: Vishay-Dale; CompType: Resistor; Value: 20.0k; Res_ohm: 20000; Value_Code: 20k0; Tolerance_%: 1; Power_W: 0.1; Value2: 0.1W; VDC_V: 75; TempCo: 100 ppm/C; SizeArea_mm2: 1.28; SizeX_mm: 1.6; SizeY_mm: 0.8; EIA_Code: E96; U/M: EA; AEC Category: Q200; Green_Lifecycle: Active; Green_REACh: Passed
R115 R119 = CRCW06030000Z0EA: RES, 0, 5%, 0.1 W, 0603; Manufacturer: Vishay-Dale; CompType: Resistor; Value: 0; Value_Code: 0000; Tolerance_%: 5; Power_W: 0.1; Value2: 0.1W; VDC_V: 75; TempCo: 200 ppm/C; SizeArea_mm2: 1.28; SizeX_mm: 1.6; SizeY_mm: 0.8; SizeZ_mm: 1; EIA_Code: E24; U/M: EA; AEC Category: Q200; Green_Lifecycle: Active; Green_REACh: Passed
R120 = CRCW06032K21FKEA: RES, 2.21 k, 1%, 0.1 W, 0603; Manufacturer: Vishay-Dale; CompType: Resistor; Res_ohm: 2210; Value_Code: 2k21; Tolerance_%: 1; Power_W: 0.1; Value2: 0.1W; VDC_V: 75; TempCo: 100 ppm/C; SizeArea_mm2: 1.28; SizeX_mm: 1.6; SizeY_mm: 0.8; EIA_Code: E96; U/M: EA; AEC Category: Q200; Green_Lifecycle: Active; Green_REACh: Passed
R121 = CRCW0603249KFKEA: RES, 249 k, 1%, 0.1 W, 0603; Manufacturer: Vishay-Dale; CompType: Resistor; Value: 249k; Res_ohm: 249000; Tolerance_%: 1; Power_W: 0.1; Value2: 0.1W; VDC_V: 75; TempCo: 100 ppm/C; SizeArea_mm2: 1.28; SizeX_mm: 1.6; SizeY_mm: 0.8; EIA_Code: E96; U/M: EA; AEC Category: Q200; Green_Lifecycle: Active; Green_REACh: Passed
R122 = CRCW060314K7FKEA: RES, 14.7 k, 1%, 0.1 W, 0603; Manufacturer: Vishay-Dale; CompType: Resistor; Value: 14.7k; Res_ohm: 14700; Value_Code: 14k7; Tolerance_%: 1; Power_W: 0.1; Value2: 0.1W; VDC_V: 75; TempCo: 100 ppm/C; SizeArea_mm2: 1.28; SizeX_mm: 1.6; SizeY_mm: 0.8; EIA_Code: E96; U/M: EA; AEC Category: Q200; Green_Lifecycle: Active; Green_REACh: Passed
R124 = CRCW06034K99FKEA: RES, 4.99 k, 1%, 0.1 W, 0603; Manufacturer: Vishay-Dale; CompType: Resistor; Value: 4.99k; Res_ohm: 4990; Value_Code: 4k99; Tolerance_%: 1; Power_W: 0.1; Value2: 0.1W; VDC_V: 75; TempCo: 100 ppm/C; SizeArea_mm2: 1.28; SizeX_mm: 1.6; SizeY_mm: 0.8; EIA_Code: E96; U/M: EA; AEC Category: Q200; Green_Lifecycle: Active; Green_REACh: Passed
R125 = CRCW060337K4FKEA: RES, 37.4 k, 1%, 0.1 W, 0603; Manufacturer: Vishay-Dale; CompType: Resistor; Res_ohm: 37400; Value_Code: 37k4; Tolerance_%: 1; Power_W: 0.1; Value2: 0.1W; VDC_V: 75; TempCo: 100 ppm/C; SizeArea_mm2: 1.28; SizeX_mm: 1.6; SizeY_mm: 0.8; EIA_Code: E96; U/M: EA; AEC Category: Q200; Green_Lifecycle: Active; Green_REACh: Passed
R126 = CRCW12068R20JNEA: RES, 8.2, 5%, 0.25 W, 1206; Manufacturer: Vishay-Dale; CompType: Resistor; Value: 8.2; Value_Code: 8R20; Tolerance_%: 5; Power_W: 0.25; Value2: 0.25W; VDC_V: 200; TempCo: 200 ppm/C; SizeArea_mm2: 5.12; SizeX_mm: 3.2; SizeY_mm: 1.6; SizeZ_mm: 1.35; EIA_Code: E24; U/M: EA; AEC Category: Q200
R127-R129 = Resistor: RES, 0.18 ohm, 1%, 500mW, current sense [PackageReference]; Manufacturer: Panasonic Electronic Components; U/M: EA
R131 R133 = CRCW0805200KJNEA: RES, 200 k, 5%, 0.125 W, 0805; Manufacturer: Vishay-Dale; CompType: Resistor; Value: 200k; Res_ohm: 200000; Tolerance_%: 5; Power_W: 0.125; Value2: 0.125W; VDC_V: 150; TempCo: 200 ppm/C; SizeArea_mm2: 2.5; SizeX_mm: 2; SizeY_mm: 1.25; SizeZ_mm: 1.45; EIA_Code: E24; U/M: EA; AEC Category: Q200
R132 = CRCW12060000Z0EA: RES, 0, 5%, 0.25 W, 1206; Manufacturer: Vishay-Dale; CompType: Resistor; Res_ohm: 0; Value_Code: 0000; Tolerance_%: 5; Power_W: 0.25; Value2: 0.25W; VDC_V: 200; TempCo: 200 ppm/C; SizeArea_mm2: 5.12; SizeX_mm: 3.2; SizeY_mm: 1.6; SizeZ_mm: 1.35; EIA_Code: E24; U/M: EA; AEC Category: Q200; Green_Lifecycle: Active; Green_REACh: Passed
R134 R135 R146 = CRCW08050000Z0EA: RES, 0, 5%, 0.125 W, 0805; Manufacturer: Vishay-Dale; CompType: Resistor; Res_ohm: 0; Value_Code: 0000; Tolerance_%: 5; Power_W: 0.125; Value2: 0.125W; VDC_V: 150; TempCo: 200 ppm/C; SizeArea_mm2: 2.5; SizeX_mm: 2; SizeY_mm: 1.25; SizeZ_mm: 1.45; EIA_Code: E24; U/M: EA; AEC Category: Q200; Green_Lifecycle: Active; Green_REACh: Passed
R136 = CRCW08050000Z0EAHP: RES, 0, 5%, 0.333 W, 0805; Manufacturer: Vishay-Dale; CompType: Resistor; Value: 0; Value_Code: 0000; Tolerance_%: 5; Power_W: 0.333; Value2: 0.333W; TempCo: 200 ppm/C; SizeArea_mm2: 2.5; SizeX_mm: 2; SizeY_mm: 1.25; SizeZ_mm: 1.45; EIA_Code: E24; U/M: EA; AEC Category: Q200; Green_Lifecycle: Active; Green_REACh: Passed
R137 R140 = CRCW12063M92FKEA: RES, 3.92 M, 1%, 0.25 W, 1206; Manufacturer: Vishay-Dale; CompType: Resistor; Res_ohm: 3920000; Value_Code: 3M92; Tolerance_%: 1; Power_W: 0.25; Value2: 0.25W; VDC_V: 200; TempCo: 100 ppm/C; SizeArea_mm2: 5.12; SizeX_mm: 3.2; SizeY_mm: 1.6; SizeZ_mm: 1.35; EIA_Code: E96; U/M: EA; AEC Category: Q200
R138 = CRCW0603249KFKEA: RES, 249 k, 1%, 0.1 W, 0603; Manufacturer: Vishay-Dale; CompType: Resistor; Res_ohm: 249000; Value_Code: 249k; Tolerance_%: 1; Power_W: 0.1; Value2: 0.1W; VDC_V: 75; TempCo: 100 ppm/C; SizeArea_mm2: 1.28; SizeX_mm: 1.6; SizeY_mm: 0.8; EIA_Code: E96; U/M: EA; AEC Category: Q200; Green_Lifecycle: Active; Green_REACh: Passed
R139 R142 = Resistor: RES, xxx ohm, x%, xW, [PackageReference]; U/M: EA
R141 R149 = CRCW0603499KFKEA: RES, 499 k, 1%, 0.1 W, 0603; Manufacturer: Vishay-Dale; CompType: Resistor; Res_ohm: 499000; Value_Code: 499k; Tolerance_%: 1; Power_W: 0.1; Value2: 0.1W; VDC_V: 75; TempCo: 100 ppm/C; SizeArea_mm2: 1.28; SizeX_mm: 1.6; SizeY_mm: 0.8; EIA_Code: E96; U/M: EA; AEC Category: Q200; Green_Lifecycle: Active; Green_REACh: Passed
R143 = CRCW0805499KFKEA: RES, 499 k, 1%, 0.125 W, 0805; Manufacturer: Vishay-Dale; CompType: Resistor; Value: 499k; Res_ohm: 499000; Tolerance_%: 1; Power_W: 0.125; Value2: 0.125W; VDC_V: 150; TempCo: 100 ppm/C; SizeArea_mm2: 2.5; SizeX_mm: 2; SizeY_mm: 1.25; SizeZ_mm: 1.45; EIA_Code: E96; U/M: EA; AEC Category: Q200; Green_Lifecycle: Active; Green_REACh: Passed
R144 R147 = CRCW06030000Z0EA: RES, 0, 5%, 0.1 W, 0603; Manufacturer: Vishay-Dale; CompType: Resistor; Res_ohm: 0; Value_Code: 0000; Tolerance_%: 5; Power_W: 0.1; Value2: 0.1W; VDC_V: 75; TempCo: 200 ppm/C; SizeArea_mm2: 1.28; SizeX_mm: 1.6; SizeY_mm: 0.8; SizeZ_mm: 1; EIA_Code: E24; U/M: EA; AEC Category: Q200; Green_Lifecycle: Active; Green_REACh: Passed
R145 = CRCW080510K0FKEA: RES, 10.0 k, 1%, 0.125 W, 0805; Manufacturer: Vishay-Dale; CompType: Resistor; Res_ohm: 10000; Value_Code: 10k0; Tolerance_%: 1; Power_W: 0.125; Value2: 0.125W; VDC_V: 150; TempCo: 100 ppm/C; SizeArea_mm2: 2.5; SizeX_mm: 2; SizeY_mm: 1.25; SizeZ_mm: 1.45; EIA_Code: E96; U/M: EA; AEC Category: Q200; Green_Lifecycle: Active; Green_REACh: Passed
R148 = CRCW0603100KFKEA: RES, 100 k, 1%, 0.1 W, 0603; Manufacturer: Vishay-Dale; CompType: Resistor; Res_ohm: 100000; Value_Code: 100k; Tolerance_%: 1; Power_W: 0.1; Value2: 0.1W; VDC_V: 75; TempCo: 100 ppm/C; SizeArea_mm2: 1.28; SizeX_mm: 1.6; SizeY_mm: 0.8; EIA_Code: E96; U/M: EA; AEC Category: Q200; Green_Lifecycle: Active; Green_REACh: Passed
R150 = CRCW0805402KFKEA: RES, 402 k, 1%, 0.125 W, 0805; Manufacturer: Vishay-Dale; CompType: Resistor; Res_ohm: 402000; Value_Code: 402k; Tolerance_%: 1; Power_W: 0.125; Value2: 0.125W; VDC_V: 150; TempCo: 100 ppm/C; SizeArea_mm2: 2.5; SizeX_mm: 2; SizeY_mm: 1.25; SizeZ_mm: 1.45; EIA_Code: E96; U/M: EA; AEC Category: Q200
RT100 RT101 = B57237S229M: Thermistor NTC, 2.2 ohm, 20%, 15x7mm; Manufacturer: TDK; Tolerance_%: 20; Power_W: 3.1; TaMin_C: -55; TaMax_C: 170; SizeAreaWB_mm2: 161.5; SizeArea_mm2: 112.5; SizeX_mm: 15; SizeY_mm: 7.5; SizeZ_mm: 47; U/M: EA
TP100 TP102 = 1503-2: Terminal, Turret, TH, Double; Manufacturer: Keystone; CompType: Turret Terminal; Green_Lifecycle: Active; Green_REACh: Passed
TP101 = CMP-0055137-1: Test Point, Miniature, Red, TH; Manufacturer: Keystone; CNHeader: FALSE; Green_Lifecycle: Active; Green_REACh: Passed; ContactFinish: Silver; CT: TRUE
TP103 = CMP-0055138-1: Test Point, Miniature, Black, TH; Manufacturer: Keystone; CNHeader: FALSE; Green_Lifecycle: Active; Green_REACh: Passed; ContactFinish: Silver; CT: TRUE
TP104 = 1508-0-57-15-00-00-03-0: PC Test Point, SMT; Manufacturer: Mill-Max; SymbolCreator: a0412235
U100 = UCC28C42DR: BiCMOS Low Current 8 Pin PWM Current Mode Controller, D0008A (SOIC-8); Manufacturer: Texas Instruments; SymbolCreator: a0411947; SizeArea_mm2: 30.38; SizeAreaWB_mm2: 56.58; SizeX_mm: 4.9; SizeY_mm: 6.2; SizeZ_mm: 1.75; CompType: IC; U/M: EA
U101 = CMP-0078944-1: Transformer, 500 uH, SMD; Manufacturer: Wurth Elektronik; SizeAreaWB_mm2: 86.33; SizeArea_mm2: 53.13; AEC Qualified: N; Lp: 500; AEC Category: Q200; Value: 500uH; SizeZ_mm: 5.33; Ind_H: 500µH; SizeY_mm: 6.9; Ns1toNp: 50; Rsec1_ohm: 1.4; DCR_ohm: 6m; SizeX_mm: 7.7
U102 = CMP-0080757-2: 40 V, microPower, Push-Pull Comparator with Shutdown, DBV0006A (SOT-23-6); Alternate Manufacturer: Texas Instruments; SizeAreaWB_mm2: 14.82; SizeZ_mm: 1.45; SizeX_mm: 2.8; SizeY_mm: 2.9; SizeArea_mm2: 8.12; CompType: IC; AEC Qualified: N; AEC Category: Q200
